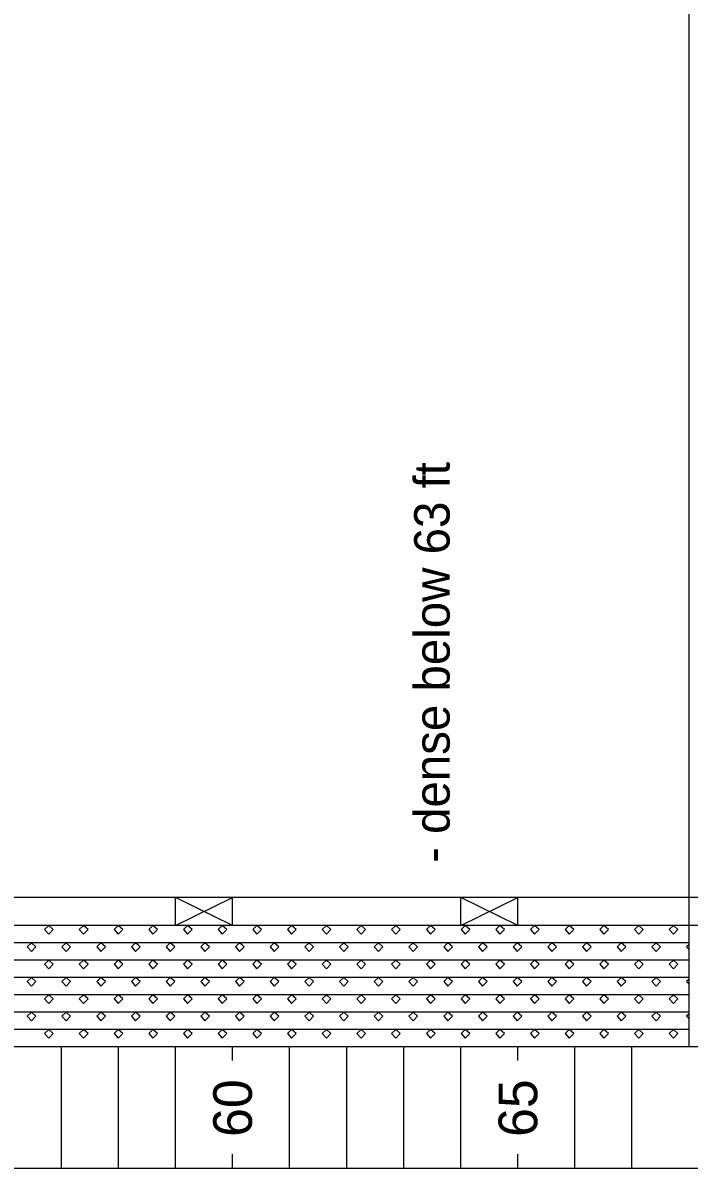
# Model space of a CAD drawing. Extents: x 1313964 to 1316843, y 2087046 to 2096619.
# Drawn here: x 1314100.62 to 1314112.29, y 2089873.43 to 2089893.52 of the extents above; entities that cross this region are included whole.
import ezdxf

# ---------------------------------------------------------------- set-up
doc = ezdxf.new("R2010")
doc.units = 0
doc.layers.add('B-Sub-Contour', color=7, linetype='Continuous')

msp = doc.modelspace()

# ---------------------------------------------------------------- linework, layer by layer
at = {"layer": 'B-Sub-Contour'}
for points in [[(1314136.725, 2089873.434), (1314136.725, 2089916.306), (1314075.306, 2089916.306), (1314075.306, 2089873.434), (1314136.725, 2089873.434)], [(1314112.292, 2089878.178), (1314112.292, 2089894.049)], [(1314134.292, 2089878.178), (1314089.292, 2089878.178)], [(1314103.292, 2089877.691), (1314104.292, 2089878.178)], [(1314104.292, 2089877.691), (1314103.292, 2089878.178)], [(1314103.292, 2089877.691), (1314103.292, 2089878.178)], [(1314104.292, 2089877.691), (1314104.292, 2089878.178)], [(1314108.292, 2089877.691), (1314109.292, 2089878.178)], [(1314109.292, 2089877.691), (1314108.292, 2089878.178)], [(1314108.292, 2089877.691), (1314108.292, 2089878.178)], [(1314109.292, 2089877.691), (1314109.292, 2089878.178)], [(1314112.292, 2089877.691), (1314112.292, 2089878.178)], [(1314134.292, 2089877.691), (1314082.603, 2089877.691)], [(1314112.292, 2089875.563), (1314112.292, 2089877.691)], [(1314112.292, 2089877.387), (1314089.292, 2089877.387)], [(1314112.292, 2089877.083), (1314089.292, 2089877.083)], [(1314112.292, 2089876.779), (1314089.292, 2089876.779)], [(1314112.292, 2089876.475), (1314089.292, 2089876.475)], [(1314112.292, 2089876.171), (1314089.292, 2089876.171)], [(1314112.292, 2089875.867), (1314089.292, 2089875.867)], [(1314134.292, 2089875.563), (1314082.603, 2089875.563)], [(1314101.292, 2089873.434), (1314101.292, 2089875.563)], [(1314102.292, 2089873.434), (1314102.292, 2089875.563)], [(1314102.292, 2089873.434), (1314102.292, 2089875.563)], [(1314103.292, 2089873.434), (1314103.292, 2089875.563)], [(1314104.292, 2089875.319), (1314104.292, 2089875.563)], [(1314104.292, 2089875.319), (1314104.292, 2089875.563)], [(1314105.292, 2089873.434), (1314105.292, 2089875.563)], [(1314106.292, 2089873.434), (1314106.292, 2089875.563)], [(1314106.292, 2089873.434), (1314106.292, 2089875.563)], [(1314107.292, 2089873.434), (1314107.292, 2089875.563)], [(1314108.292, 2089873.434), (1314108.292, 2089875.563)], [(1314108.292, 2089873.434), (1314108.292, 2089875.563)], [(1314109.292, 2089875.319), (1314109.292, 2089875.563)], [(1314110.292, 2089873.434), (1314110.292, 2089875.563)], [(1314110.292, 2089873.434), (1314110.292, 2089875.563)], [(1314111.292, 2089873.434), (1314111.292, 2089875.563)], [(1314104.292, 2089873.434), (1314104.292, 2089873.678)], [(1314104.292, 2089873.434), (1314104.292, 2089873.678)], [(1314109.292, 2089873.434), (1314109.292, 2089873.678)]]:
    msp.add_lwpolyline(points, dxfattribs=at)
for points in [[(1314101.071, 2089877.691), (1314100.999, 2089877.618), (1314101.071, 2089877.539), (1314101.151, 2089877.618)], [(1314101.68, 2089877.691), (1314101.607, 2089877.618), (1314101.68, 2089877.539), (1314101.759, 2089877.618)], [(1314102.288, 2089877.691), (1314102.215, 2089877.618), (1314102.288, 2089877.539), (1314102.367, 2089877.618)], [(1314102.896, 2089877.691), (1314102.823, 2089877.618), (1314102.896, 2089877.539), (1314102.975, 2089877.618)], [(1314103.504, 2089877.691), (1314103.431, 2089877.618), (1314103.504, 2089877.539), (1314103.583, 2089877.618)], [(1314104.112, 2089877.691), (1314104.039, 2089877.618), (1314104.112, 2089877.539), (1314104.191, 2089877.618)], [(1314104.72, 2089877.691), (1314104.647, 2089877.618), (1314104.72, 2089877.539), (1314104.799, 2089877.618)], [(1314105.328, 2089877.691), (1314105.255, 2089877.618), (1314105.328, 2089877.539), (1314105.407, 2089877.618)], [(1314105.936, 2089877.691), (1314105.863, 2089877.618), (1314105.936, 2089877.539), (1314106.015, 2089877.618)], [(1314106.544, 2089877.691), (1314106.471, 2089877.618), (1314106.544, 2089877.539), (1314106.624, 2089877.618)], [(1314107.153, 2089877.691), (1314107.08, 2089877.618), (1314107.153, 2089877.539), (1314107.232, 2089877.618)], [(1314107.761, 2089877.691), (1314107.688, 2089877.618), (1314107.761, 2089877.539), (1314107.84, 2089877.618)], [(1314108.369, 2089877.691), (1314108.296, 2089877.618), (1314108.369, 2089877.539), (1314108.448, 2089877.618)], [(1314108.977, 2089877.691), (1314108.904, 2089877.618), (1314108.977, 2089877.539), (1314109.056, 2089877.618)], [(1314109.585, 2089877.691), (1314109.512, 2089877.618), (1314109.585, 2089877.539), (1314109.664, 2089877.618)], [(1314110.193, 2089877.691), (1314110.12, 2089877.618), (1314110.193, 2089877.539), (1314110.272, 2089877.618)], [(1314110.801, 2089877.691), (1314110.728, 2089877.618), (1314110.801, 2089877.539), (1314110.88, 2089877.618)], [(1314111.409, 2089877.691), (1314111.336, 2089877.618), (1314111.409, 2089877.539), (1314111.488, 2089877.618)], [(1314112.017, 2089877.691), (1314111.944, 2089877.618), (1314112.017, 2089877.539), (1314112.096, 2089877.618)], [(1314100.767, 2089877.387), (1314100.694, 2089877.314), (1314100.767, 2089877.235), (1314100.846, 2089877.314)], [(1314101.376, 2089877.387), (1314101.303, 2089877.314), (1314101.376, 2089877.235), (1314101.455, 2089877.314)], [(1314101.984, 2089877.387), (1314101.911, 2089877.314), (1314101.984, 2089877.235), (1314102.063, 2089877.314)], [(1314102.592, 2089877.387), (1314102.519, 2089877.314), (1314102.592, 2089877.235), (1314102.671, 2089877.314)], [(1314103.2, 2089877.387), (1314103.127, 2089877.314), (1314103.2, 2089877.235), (1314103.279, 2089877.314)], [(1314103.808, 2089877.387), (1314103.735, 2089877.314), (1314103.808, 2089877.235), (1314103.887, 2089877.314)], [(1314104.416, 2089877.387), (1314104.343, 2089877.314), (1314104.416, 2089877.235), (1314104.495, 2089877.314)], [(1314105.024, 2089877.387), (1314104.951, 2089877.314), (1314105.024, 2089877.235), (1314105.103, 2089877.314)], [(1314105.632, 2089877.387), (1314105.559, 2089877.314), (1314105.632, 2089877.235), (1314105.711, 2089877.314)], [(1314106.24, 2089877.387), (1314106.167, 2089877.314), (1314106.24, 2089877.235), (1314106.319, 2089877.314)], [(1314106.849, 2089877.387), (1314106.776, 2089877.314), (1314106.849, 2089877.235), (1314106.928, 2089877.314)], [(1314107.457, 2089877.387), (1314107.384, 2089877.314), (1314107.457, 2089877.235), (1314107.536, 2089877.314)], [(1314108.065, 2089877.387), (1314107.992, 2089877.314), (1314108.065, 2089877.235), (1314108.144, 2089877.314)], [(1314108.673, 2089877.387), (1314108.6, 2089877.314), (1314108.673, 2089877.235), (1314108.752, 2089877.314)], [(1314109.281, 2089877.387), (1314109.208, 2089877.314), (1314109.281, 2089877.235), (1314109.36, 2089877.314)], [(1314109.889, 2089877.387), (1314109.816, 2089877.314), (1314109.889, 2089877.235), (1314109.968, 2089877.314)], [(1314110.497, 2089877.387), (1314110.424, 2089877.314), (1314110.497, 2089877.235), (1314110.576, 2089877.314)], [(1314111.105, 2089877.387), (1314111.032, 2089877.314), (1314111.105, 2089877.235), (1314111.184, 2089877.314)], [(1314111.713, 2089877.387), (1314111.64, 2089877.314), (1314111.713, 2089877.235), (1314111.792, 2089877.314)], [(1314112.248, 2089877.314), (1314112.292, 2089877.266), (1314112.292, 2089877.358), (1314112.248, 2089877.314)], [(1314101.071, 2089877.083), (1314100.999, 2089877.01), (1314101.071, 2089876.931), (1314101.151, 2089877.01)], [(1314101.68, 2089877.083), (1314101.607, 2089877.01), (1314101.68, 2089876.931), (1314101.759, 2089877.01)], [(1314102.288, 2089877.083), (1314102.215, 2089877.01), (1314102.288, 2089876.931), (1314102.367, 2089877.01)], [(1314102.896, 2089877.083), (1314102.823, 2089877.01), (1314102.896, 2089876.931), (1314102.975, 2089877.01)], [(1314103.504, 2089877.083), (1314103.431, 2089877.01), (1314103.504, 2089876.931), (1314103.583, 2089877.01)], [(1314104.112, 2089877.083), (1314104.039, 2089877.01), (1314104.112, 2089876.931), (1314104.191, 2089877.01)], [(1314104.72, 2089877.083), (1314104.647, 2089877.01), (1314104.72, 2089876.931), (1314104.799, 2089877.01)], [(1314105.328, 2089877.083), (1314105.255, 2089877.01), (1314105.328, 2089876.931), (1314105.407, 2089877.01)], [(1314105.936, 2089877.083), (1314105.863, 2089877.01), (1314105.936, 2089876.931), (1314106.015, 2089877.01)], [(1314106.544, 2089877.083), (1314106.471, 2089877.01), (1314106.544, 2089876.931), (1314106.624, 2089877.01)], [(1314107.153, 2089877.083), (1314107.08, 2089877.01), (1314107.153, 2089876.931), (1314107.232, 2089877.01)], [(1314107.761, 2089877.083), (1314107.688, 2089877.01), (1314107.761, 2089876.931), (1314107.84, 2089877.01)], [(1314108.369, 2089877.083), (1314108.296, 2089877.01), (1314108.369, 2089876.931), (1314108.448, 2089877.01)], [(1314108.977, 2089877.083), (1314108.904, 2089877.01), (1314108.977, 2089876.931), (1314109.056, 2089877.01)], [(1314109.585, 2089877.083), (1314109.512, 2089877.01), (1314109.585, 2089876.931), (1314109.664, 2089877.01)], [(1314110.193, 2089877.083), (1314110.12, 2089877.01), (1314110.193, 2089876.931), (1314110.272, 2089877.01)], [(1314110.801, 2089877.083), (1314110.728, 2089877.01), (1314110.801, 2089876.931), (1314110.88, 2089877.01)], [(1314111.409, 2089877.083), (1314111.336, 2089877.01), (1314111.409, 2089876.931), (1314111.488, 2089877.01)], [(1314112.017, 2089877.083), (1314111.944, 2089877.01), (1314112.017, 2089876.931), (1314112.096, 2089877.01)], [(1314100.767, 2089876.779), (1314100.694, 2089876.706), (1314100.767, 2089876.627), (1314100.846, 2089876.706)], [(1314101.376, 2089876.779), (1314101.303, 2089876.706), (1314101.376, 2089876.627), (1314101.455, 2089876.706)], [(1314101.984, 2089876.779), (1314101.911, 2089876.706), (1314101.984, 2089876.627), (1314102.063, 2089876.706)], [(1314102.592, 2089876.779), (1314102.519, 2089876.706), (1314102.592, 2089876.627), (1314102.671, 2089876.706)], [(1314103.2, 2089876.779), (1314103.127, 2089876.706), (1314103.2, 2089876.627), (1314103.279, 2089876.706)], [(1314103.808, 2089876.779), (1314103.735, 2089876.706), (1314103.808, 2089876.627), (1314103.887, 2089876.706)], [(1314104.416, 2089876.779), (1314104.343, 2089876.706), (1314104.416, 2089876.627), (1314104.495, 2089876.706)], [(1314105.024, 2089876.779), (1314104.951, 2089876.706), (1314105.024, 2089876.627), (1314105.103, 2089876.706)], [(1314105.632, 2089876.779), (1314105.559, 2089876.706), (1314105.632, 2089876.627), (1314105.711, 2089876.706)], [(1314106.24, 2089876.779), (1314106.167, 2089876.706), (1314106.24, 2089876.627), (1314106.319, 2089876.706)], [(1314106.849, 2089876.779), (1314106.776, 2089876.706), (1314106.849, 2089876.627), (1314106.928, 2089876.706)], [(1314107.457, 2089876.779), (1314107.384, 2089876.706), (1314107.457, 2089876.627), (1314107.536, 2089876.706)], [(1314108.065, 2089876.779), (1314107.992, 2089876.706), (1314108.065, 2089876.627), (1314108.144, 2089876.706)], [(1314108.673, 2089876.779), (1314108.6, 2089876.706), (1314108.673, 2089876.627), (1314108.752, 2089876.706)], [(1314109.281, 2089876.779), (1314109.208, 2089876.706), (1314109.281, 2089876.627), (1314109.36, 2089876.706)], [(1314109.889, 2089876.779), (1314109.816, 2089876.706), (1314109.889, 2089876.627), (1314109.968, 2089876.706)], [(1314110.497, 2089876.779), (1314110.424, 2089876.706), (1314110.497, 2089876.627), (1314110.576, 2089876.706)], [(1314111.105, 2089876.779), (1314111.032, 2089876.706), (1314111.105, 2089876.627), (1314111.184, 2089876.706)], [(1314111.713, 2089876.779), (1314111.64, 2089876.706), (1314111.713, 2089876.627), (1314111.792, 2089876.706)], [(1314112.248, 2089876.706), (1314112.292, 2089876.658), (1314112.292, 2089876.75), (1314112.248, 2089876.706)], [(1314101.071, 2089876.475), (1314100.999, 2089876.402), (1314101.071, 2089876.323), (1314101.151, 2089876.402)], [(1314101.68, 2089876.475), (1314101.607, 2089876.402), (1314101.68, 2089876.323), (1314101.759, 2089876.402)], [(1314102.288, 2089876.475), (1314102.215, 2089876.402), (1314102.288, 2089876.323), (1314102.367, 2089876.402)], [(1314102.896, 2089876.475), (1314102.823, 2089876.402), (1314102.896, 2089876.323), (1314102.975, 2089876.402)], [(1314103.504, 2089876.475), (1314103.431, 2089876.402), (1314103.504, 2089876.323), (1314103.583, 2089876.402)], [(1314104.112, 2089876.475), (1314104.039, 2089876.402), (1314104.112, 2089876.323), (1314104.191, 2089876.402)], [(1314104.72, 2089876.475), (1314104.647, 2089876.402), (1314104.72, 2089876.323), (1314104.799, 2089876.402)], [(1314105.328, 2089876.475), (1314105.255, 2089876.402), (1314105.328, 2089876.323), (1314105.407, 2089876.402)], [(1314105.936, 2089876.475), (1314105.863, 2089876.402), (1314105.936, 2089876.323), (1314106.015, 2089876.402)], [(1314106.544, 2089876.475), (1314106.471, 2089876.402), (1314106.544, 2089876.323), (1314106.624, 2089876.402)], [(1314107.153, 2089876.475), (1314107.08, 2089876.402), (1314107.153, 2089876.323), (1314107.232, 2089876.402)], [(1314107.761, 2089876.475), (1314107.688, 2089876.402), (1314107.761, 2089876.323), (1314107.84, 2089876.402)], [(1314108.369, 2089876.475), (1314108.296, 2089876.402), (1314108.369, 2089876.323), (1314108.448, 2089876.402)], [(1314108.977, 2089876.475), (1314108.904, 2089876.402), (1314108.977, 2089876.323), (1314109.056, 2089876.402)], [(1314109.585, 2089876.475), (1314109.512, 2089876.402), (1314109.585, 2089876.323), (1314109.664, 2089876.402)], [(1314110.193, 2089876.475), (1314110.12, 2089876.402), (1314110.193, 2089876.323), (1314110.272, 2089876.402)], [(1314110.801, 2089876.475), (1314110.728, 2089876.402), (1314110.801, 2089876.323), (1314110.88, 2089876.402)], [(1314111.409, 2089876.475), (1314111.336, 2089876.402), (1314111.409, 2089876.323), (1314111.488, 2089876.402)], [(1314112.017, 2089876.475), (1314111.944, 2089876.402), (1314112.017, 2089876.323), (1314112.096, 2089876.402)], [(1314100.767, 2089876.171), (1314100.694, 2089876.098), (1314100.767, 2089876.019), (1314100.846, 2089876.098)], [(1314101.376, 2089876.171), (1314101.303, 2089876.098), (1314101.376, 2089876.019), (1314101.455, 2089876.098)], [(1314101.984, 2089876.171), (1314101.911, 2089876.098), (1314101.984, 2089876.019), (1314102.063, 2089876.098)], [(1314102.592, 2089876.171), (1314102.519, 2089876.098), (1314102.592, 2089876.019), (1314102.671, 2089876.098)], [(1314103.2, 2089876.171), (1314103.127, 2089876.098), (1314103.2, 2089876.019), (1314103.279, 2089876.098)], [(1314103.808, 2089876.171), (1314103.735, 2089876.098), (1314103.808, 2089876.019), (1314103.887, 2089876.098)], [(1314104.416, 2089876.171), (1314104.343, 2089876.098), (1314104.416, 2089876.019), (1314104.495, 2089876.098)], [(1314105.024, 2089876.171), (1314104.951, 2089876.098), (1314105.024, 2089876.019), (1314105.103, 2089876.098)], [(1314105.632, 2089876.171), (1314105.559, 2089876.098), (1314105.632, 2089876.019), (1314105.711, 2089876.098)], [(1314106.24, 2089876.171), (1314106.167, 2089876.098), (1314106.24, 2089876.019), (1314106.319, 2089876.098)], [(1314106.849, 2089876.171), (1314106.776, 2089876.098), (1314106.849, 2089876.019), (1314106.928, 2089876.098)], [(1314107.457, 2089876.171), (1314107.384, 2089876.098), (1314107.457, 2089876.019), (1314107.536, 2089876.098)], [(1314108.065, 2089876.171), (1314107.992, 2089876.098), (1314108.065, 2089876.019), (1314108.144, 2089876.098)], [(1314108.673, 2089876.171), (1314108.6, 2089876.098), (1314108.673, 2089876.019), (1314108.752, 2089876.098)], [(1314109.281, 2089876.171), (1314109.208, 2089876.098), (1314109.281, 2089876.019), (1314109.36, 2089876.098)], [(1314109.889, 2089876.171), (1314109.816, 2089876.098), (1314109.889, 2089876.019), (1314109.968, 2089876.098)], [(1314110.497, 2089876.171), (1314110.424, 2089876.098), (1314110.497, 2089876.019), (1314110.576, 2089876.098)], [(1314111.105, 2089876.171), (1314111.032, 2089876.098), (1314111.105, 2089876.019), (1314111.184, 2089876.098)], [(1314111.713, 2089876.171), (1314111.64, 2089876.098), (1314111.713, 2089876.019), (1314111.792, 2089876.098)], [(1314112.248, 2089876.098), (1314112.292, 2089876.05), (1314112.292, 2089876.142), (1314112.248, 2089876.098)], [(1314101.071, 2089875.867), (1314100.999, 2089875.794), (1314101.071, 2089875.715), (1314101.151, 2089875.794)], [(1314101.68, 2089875.867), (1314101.607, 2089875.794), (1314101.68, 2089875.715), (1314101.759, 2089875.794)], [(1314102.288, 2089875.867), (1314102.215, 2089875.794), (1314102.288, 2089875.715), (1314102.367, 2089875.794)], [(1314102.896, 2089875.867), (1314102.823, 2089875.794), (1314102.896, 2089875.715), (1314102.975, 2089875.794)], [(1314103.504, 2089875.867), (1314103.431, 2089875.794), (1314103.504, 2089875.715), (1314103.583, 2089875.794)], [(1314104.112, 2089875.867), (1314104.039, 2089875.794), (1314104.112, 2089875.715), (1314104.191, 2089875.794)], [(1314104.72, 2089875.867), (1314104.647, 2089875.794), (1314104.72, 2089875.715), (1314104.799, 2089875.794)], [(1314105.328, 2089875.867), (1314105.255, 2089875.794), (1314105.328, 2089875.715), (1314105.407, 2089875.794)], [(1314105.936, 2089875.867), (1314105.863, 2089875.794), (1314105.936, 2089875.715), (1314106.015, 2089875.794)], [(1314106.544, 2089875.867), (1314106.471, 2089875.794), (1314106.544, 2089875.715), (1314106.624, 2089875.794)], [(1314107.153, 2089875.867), (1314107.08, 2089875.794), (1314107.153, 2089875.715), (1314107.232, 2089875.794)], [(1314107.761, 2089875.867), (1314107.688, 2089875.794), (1314107.761, 2089875.715), (1314107.84, 2089875.794)], [(1314108.369, 2089875.867), (1314108.296, 2089875.794), (1314108.369, 2089875.715), (1314108.448, 2089875.794)], [(1314108.977, 2089875.867), (1314108.904, 2089875.794), (1314108.977, 2089875.715), (1314109.056, 2089875.794)], [(1314109.585, 2089875.867), (1314109.512, 2089875.794), (1314109.585, 2089875.715), (1314109.664, 2089875.794)], [(1314110.193, 2089875.867), (1314110.12, 2089875.794), (1314110.193, 2089875.715), (1314110.272, 2089875.794)], [(1314110.801, 2089875.867), (1314110.728, 2089875.794), (1314110.801, 2089875.715), (1314110.88, 2089875.794)], [(1314111.409, 2089875.867), (1314111.336, 2089875.794), (1314111.409, 2089875.715), (1314111.488, 2089875.794)], [(1314112.017, 2089875.867), (1314111.944, 2089875.794), (1314112.017, 2089875.715), (1314112.096, 2089875.794)]]:
    msp.add_lwpolyline(points, close=True, dxfattribs=at)

# ---------------------------------------------------------------- texts
for s, height, p in [('- dense below 63 ft', 0.62209, (1314108.097, 2089878.786)), ('60', 0.6786, (1314104.632, 2089873.982)), ('60', 0.6786, (1314104.632, 2089873.982)), ('65', 0.6786, (1314109.632, 2089873.982))]:
    msp.add_text(s, height=height, rotation=90, dxfattribs=at).set_placement(p)

doc.saveas('drawing.dxf')
